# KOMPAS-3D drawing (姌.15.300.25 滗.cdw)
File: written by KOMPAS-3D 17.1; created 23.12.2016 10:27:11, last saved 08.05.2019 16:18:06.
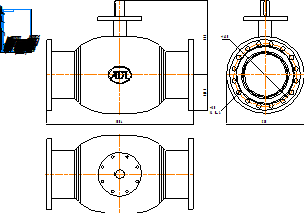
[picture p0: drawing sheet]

Sheet 1: A4, portrait

Title block, sheet 1: name: КШ.15.300.25 фф; material: Внимание! Данный продукт является объектом авторского права ООО «Торговый Дом АДЛ». / Запрещается изменение, копирование, распространение / (в том числе путем копирования на другие сайты и ресурсы в Интернете) / или любое иное использование информации и объектов без предварительного / согласия правообладателя (ООО «Торговый Дом АДЛ»).; sheets: 1; organisation: ООО "Торговый дом АДЛ"; sheet format: A4; stored path: C:\Users\tra\Desktop\2д чертежи\Шаровые краны БИВАЛ\КШ_Бивал_серия_14_15\KOMPAS_2D\КШ.15.300.25 фф.cdw

Views: Вид 1, Проекционный вид 3
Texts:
  Klimkovich
  ADL
Dimensions and other numbers on the sheet: 1004; 505; 242,5; 430; 1:1; 1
